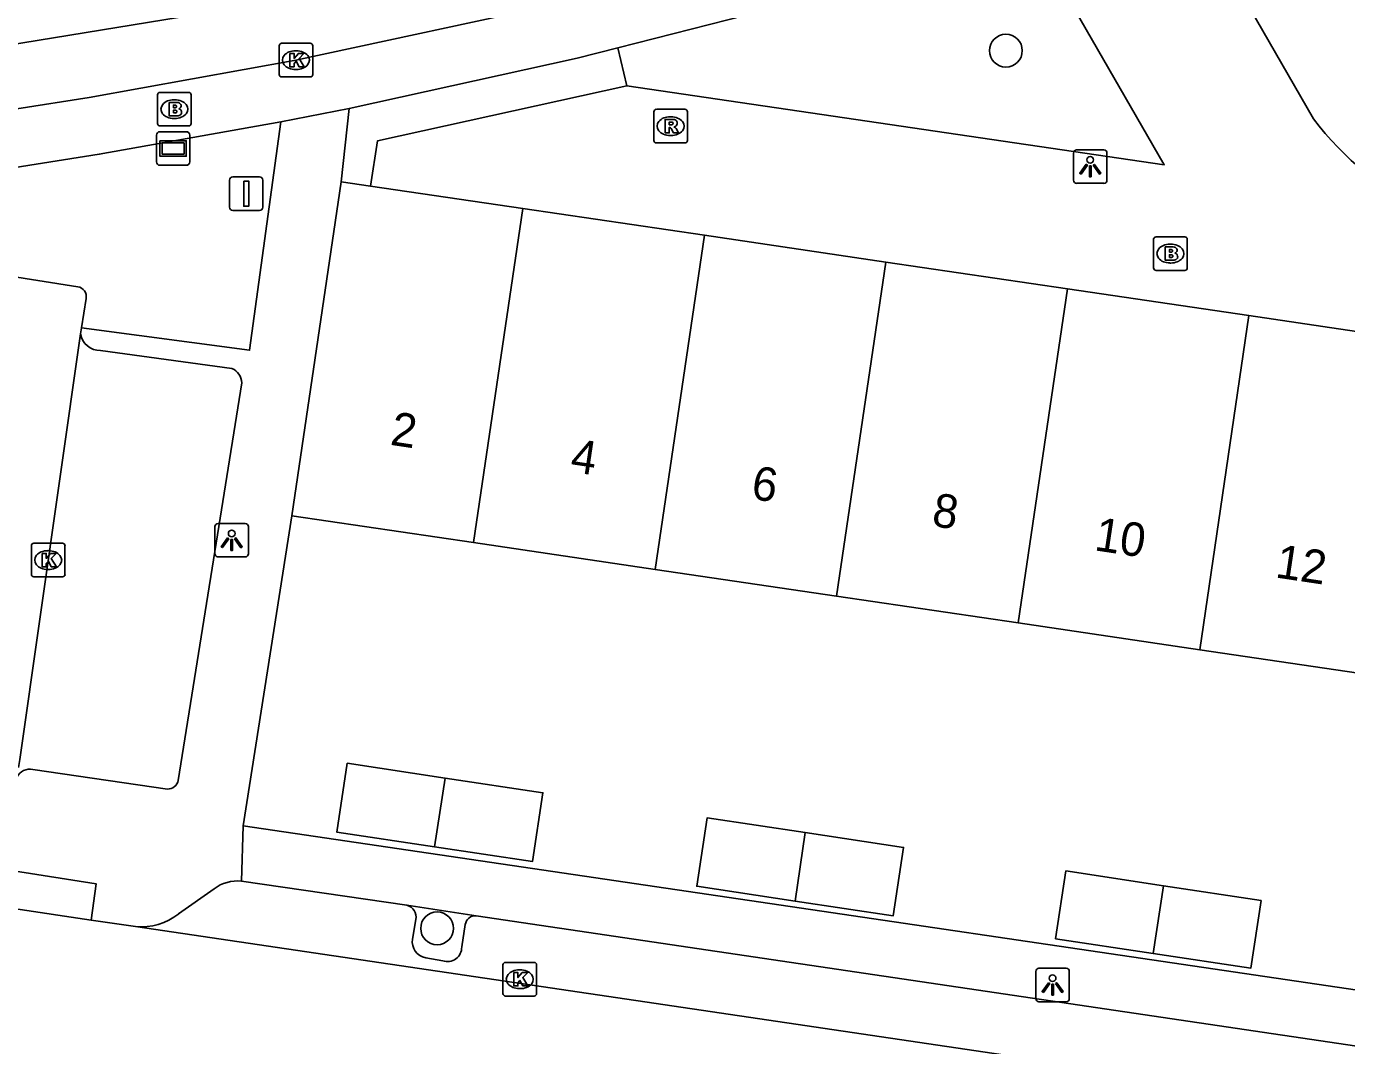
# Model space of a CAD drawing. Extents: x 164150 to 165261, y 382513 to 383432.
# Drawn here: x 164377.35 to 164416.63, y 383340.94 to 383371.28 of the extents above; entities that cross this region are included whole.
import ezdxf

# ---------------------------------------------------------------- set-up
doc = ezdxf.new("R2010")
doc.units = 0
for name, color, linetype in [('IMGEO_Boom', 7, 'Continuous'), ('IMGEO_Brandkraan', 7, 'Continuous'), ('IMGEO_Kolk', 7, 'Continuous'), ('IMGEO_Lichtpunt', 7, 'Continuous'), ('IMGEO_Pand', 7, 'Continuous'), ('IMGEO_Pand_nummerreeks', 7, 'Continuous'), ('IMGEO_Parkeervlak_open', 7, 'Continuous'), ('IMGEO_Rijbaan_lokaal_gesloten', 7, 'Continuous'), ('IMGEO_Rijbaan_lokaal_open', 7, 'Continuous'), ('IMGEO_Rioolput', 7, 'Continuous'), ('IMGEO_Verkeersbordpaal', 7, 'Continuous'), ('IMGEO_Verklikker', 7, 'Continuous'), ('IMGEO_Voetpad_op_trap', 7, 'Continuous'), ('IMGEO_Voetpad_open', 7, 'Continuous')]:
    doc.layers.add(name, color=color, linetype=linetype)

msp = doc.modelspace()

# ---------------------------------------------------------------- linework, layer by layer
at = {"layer": 'IMGEO_Boom'}
for centre in [(164406.495, 383370.556), (164389.572, 383344.434)]:
    msp.add_circle(centre, 0.489, dxfattribs=at)
at = {"layer": 'IMGEO_Brandkraan'}
for p, q in [((164381.254, 383368.389), (164381.254, 383369.241)), ((164381.329, 383369.315), (164382.181, 383369.315)), ((164382.255, 383369.241), (164382.255, 383368.389)), ((164381.742, 383369.095), (164381.767, 383369.095)), ((164381.765, 383368.535), (164381.74, 383368.535)), ((164382.181, 383368.315), (164381.329, 383368.315)), ((164410.89, 383364.09), (164410.89, 383364.942)), ((164410.965, 383365.016), (164411.817, 383365.016)), ((164411.891, 383364.942), (164411.891, 383364.09)), ((164411.378, 383364.796), (164411.403, 383364.796)), ((164411.401, 383364.236), (164411.376, 383364.236)), ((164411.817, 383364.016), (164410.965, 383364.016))]:
    msp.add_line(p, q, dxfattribs=at)
for points in [[(164381.254, 383368.389), (164381.254, 383369.241)], [(164381.329, 383369.315), (164382.181, 383369.315)], [(164382.255, 383369.241), (164382.255, 383368.389)], [(164381.602, 383369.015), (164381.602, 383368.615), (164381.815, 383368.615)], [(164381.833, 383369.015), (164381.602, 383369.015)], [(164381.781, 383368.934), (164381.727, 383368.934), (164381.727, 383368.858)], [(164381.727, 383368.858), (164381.78, 383368.858)], [(164381.789, 383368.782), (164381.727, 383368.782), (164381.727, 383368.701)], [(164381.727, 383368.701), (164381.789, 383368.701)], [(164382.181, 383368.315), (164381.329, 383368.315)], [(164410.89, 383364.09), (164410.89, 383364.942)], [(164410.965, 383365.016), (164411.817, 383365.016)], [(164411.891, 383364.942), (164411.891, 383364.09)], [(164411.238, 383364.716), (164411.238, 383364.316), (164411.451, 383364.316)], [(164411.469, 383364.716), (164411.238, 383364.716)], [(164411.417, 383364.635), (164411.363, 383364.635), (164411.363, 383364.559)], [(164411.363, 383364.559), (164411.416, 383364.559)], [(164411.425, 383364.483), (164411.363, 383364.483), (164411.363, 383364.402)], [(164411.363, 383364.402), (164411.425, 383364.402)], [(164411.817, 383364.016), (164410.965, 383364.016)]]:
    msp.add_lwpolyline(points, dxfattribs=at)
for centre, radius, start, end in [((164381.331, 383369.239), 0.0765, 91.552, 178.448), ((164381.331, 383369.239), 0.0765, 91.552, 178.448), ((164382.179, 383369.239), 0.0765, 1.552, 88.448), ((164382.179, 383369.239), 0.0765, 1.552, 88.448), ((164381.782, 383368.896), 0.0379, 267.8285, 90.9355), ((164381.837, 383368.87), 0.145, 59.4692, 91.5367), ((164381.862, 383368.917), 0.0922, 285.5137, 58.1501), ((164381.867, 383368.725), 0.105, 301.3115, 78.989), ((164381.79, 383368.741), 0.0404, 269.8759, 90.5077), ((164381.821, 383368.866), 0.251, 268.6676, 293.5347), ((164381.331, 383368.391), 0.0765, 181.552, 268.448), ((164381.331, 383368.391), 0.0765, 181.552, 268.448), ((164382.179, 383368.391), 0.0765, 271.552, 358.448), ((164382.179, 383368.391), 0.0765, 271.552, 358.448), ((164410.967, 383364.94), 0.0765, 91.552, 178.448), ((164410.967, 383364.94), 0.0765, 91.552, 178.448), ((164411.815, 383364.94), 0.0765, 1.552, 88.448), ((164411.815, 383364.94), 0.0765, 1.552, 88.448), ((164411.418, 383364.597), 0.0379, 267.8285, 90.9355), ((164411.473, 383364.571), 0.145, 59.4692, 91.5367), ((164411.498, 383364.618), 0.0922, 285.5137, 58.1501), ((164411.503, 383364.426), 0.105, 301.3115, 78.989), ((164411.426, 383364.442), 0.0404, 269.8759, 90.5077), ((164411.457, 383364.567), 0.251, 268.6676, 293.5347), ((164410.967, 383364.092), 0.0765, 181.552, 268.448), ((164410.967, 383364.092), 0.0765, 181.552, 268.448), ((164411.815, 383364.092), 0.0765, 271.552, 358.448), ((164411.815, 383364.092), 0.0765, 271.552, 358.448)]:
    msp.add_arc(centre, radius, start, end, dxfattribs=at)
for centre, major_axis, ratio, start_param, end_param in [((164381.741, 383368.815), (-0.387, 0.002), 0.722429, 4.712389, 7.853982), ((164381.766, 383368.815), (-0.39, 0.002), 0.717154, 1.570796, 4.712389), ((164411.377, 383364.516), (-0.387, 0.002), 0.722429, 4.712389, 7.853982), ((164411.402, 383364.516), (-0.39, 0.002), 0.717154, 1.570796, 4.712389)]:
    msp.add_ellipse(centre, major_axis=major_axis, ratio=ratio, start_param=start_param, end_param=end_param, dxfattribs=at)
at = {"layer": 'IMGEO_Kolk'}
for p, q in [((164384.871, 383369.849), (164384.871, 383370.701)), ((164384.946, 383370.775), (164385.798, 383370.775)), ((164385.359, 383370.555), (164385.384, 383370.555)), ((164385.872, 383370.701), (164385.872, 383369.849)), ((164385.798, 383369.775), (164384.946, 383369.775)), ((164385.382, 383369.995), (164385.357, 383369.995)), ((164377.574, 383355.895), (164378.426, 383355.895)), ((164377.499, 383354.969), (164377.499, 383355.821)), ((164377.987, 383355.675), (164378.012, 383355.675)), ((164378.5, 383355.821), (164378.5, 383354.969)), ((164378.01, 383355.115), (164377.985, 383355.115)), ((164378.426, 383354.895), (164377.574, 383354.895)), ((164391.53, 383342.493), (164391.53, 383343.345)), ((164391.605, 383343.419), (164392.457, 383343.419)), ((164392.531, 383343.345), (164392.531, 383342.493)), ((164392.018, 383343.199), (164392.043, 383343.199)), ((164392.041, 383342.639), (164392.016, 383342.639)), ((164392.457, 383342.419), (164391.605, 383342.419))]:
    msp.add_line(p, q, dxfattribs=at)
for points in [[(164384.871, 383369.849), (164384.871, 383370.701)], [(164384.946, 383370.775), (164385.798, 383370.775)], [(164385.192, 383370.475), (164385.315, 383370.475), (164385.315, 383370.324), (164385.445, 383370.475), (164385.609, 383370.475), (164385.463, 383370.324), (164385.616, 383370.075), (164385.464, 383370.075), (164385.379, 383370.239), (164385.315, 383370.172), (164385.315, 383370.075), (164385.192, 383370.075), (164385.192, 383370.475)], [(164385.872, 383370.701), (164385.872, 383369.849)], [(164385.798, 383369.775), (164384.946, 383369.775)], [(164377.574, 383355.895), (164378.426, 383355.895)], [(164377.499, 383354.969), (164377.499, 383355.821)], [(164377.82, 383355.595), (164377.943, 383355.595), (164377.943, 383355.444), (164378.073, 383355.595), (164378.237, 383355.595), (164378.091, 383355.444), (164378.244, 383355.195), (164378.092, 383355.195), (164378.007, 383355.359), (164377.943, 383355.292), (164377.943, 383355.195), (164377.82, 383355.195), (164377.82, 383355.595)], [(164378.5, 383355.821), (164378.5, 383354.969)], [(164378.426, 383354.895), (164377.574, 383354.895)], [(164391.53, 383342.493), (164391.53, 383343.345)], [(164391.605, 383343.419), (164392.457, 383343.419)], [(164392.531, 383343.345), (164392.531, 383342.493)], [(164391.851, 383343.119), (164391.974, 383343.119), (164391.974, 383342.968), (164392.104, 383343.119), (164392.268, 383343.119), (164392.122, 383342.968), (164392.275, 383342.719), (164392.123, 383342.719), (164392.038, 383342.883), (164391.974, 383342.816), (164391.974, 383342.719), (164391.851, 383342.719), (164391.851, 383343.119)], [(164392.457, 383342.419), (164391.605, 383342.419)]]:
    msp.add_lwpolyline(points, dxfattribs=at)
for centre, start, end in [((164384.948, 383370.699), 91.552, 178.448), ((164384.948, 383370.699), 91.552, 178.448), ((164385.796, 383370.699), 1.552, 88.448), ((164385.796, 383370.699), 1.552, 88.448), ((164384.948, 383369.851), 181.552, 268.448), ((164384.948, 383369.851), 181.552, 268.448), ((164385.796, 383369.851), 271.552, 358.448), ((164385.796, 383369.851), 271.552, 358.448), ((164377.576, 383355.819), 91.552, 178.448), ((164377.576, 383355.819), 91.552, 178.448), ((164378.424, 383355.819), 1.552, 88.448), ((164378.424, 383355.819), 1.552, 88.448), ((164377.576, 383354.971), 181.552, 268.448), ((164377.576, 383354.971), 181.552, 268.448), ((164378.424, 383354.971), 271.552, 358.448), ((164378.424, 383354.971), 271.552, 358.448), ((164391.607, 383343.343), 91.552, 178.448), ((164391.607, 383343.343), 91.552, 178.448), ((164392.455, 383343.343), 1.552, 88.448), ((164392.455, 383343.343), 1.552, 88.448), ((164391.607, 383342.495), 181.552, 268.448), ((164391.607, 383342.495), 181.552, 268.448), ((164392.455, 383342.495), 271.552, 358.448), ((164392.455, 383342.495), 271.552, 358.448)]:
    msp.add_arc(centre, 0.0765, start, end, dxfattribs=at)
for centre, major_axis, ratio, start_param, end_param in [((164385.358, 383370.275), (-0.387, 0.002), 0.722429, 4.712389, 7.853982), ((164385.383, 383370.275), (-0.39, 0.002), 0.717154, 1.570796, 4.712389), ((164377.986, 383355.395), (-0.387, 0.002), 0.722429, 4.712389, 7.853982), ((164378.011, 383355.395), (-0.39, 0.002), 0.717154, 1.570796, 4.712389), ((164392.017, 383342.919), (-0.387, 0.002), 0.722429, 4.712389, 7.853982), ((164392.042, 383342.919), (-0.39, 0.002), 0.717154, 1.570796, 4.712389)]:
    msp.add_ellipse(centre, major_axis=major_axis, ratio=ratio, start_param=start_param, end_param=end_param, dxfattribs=at)
at = {"layer": 'IMGEO_Lichtpunt'}
for p, q in [((164408.507, 383367.509), (164408.507, 383366.702)), ((164408.507, 383367.509), (164408.507, 383366.702)), ((164409.409, 383367.604), (164408.601, 383367.604)), ((164409.409, 383367.604), (164408.601, 383367.604)), ((164409.503, 383366.702), (164409.503, 383367.509)), ((164409.503, 383366.702), (164409.503, 383367.509)), ((164408.601, 383366.608), (164409.409, 383366.608)), ((164408.601, 383366.608), (164409.409, 383366.608)), ((164382.961, 383356.39), (164382.961, 383355.583)), ((164382.961, 383356.39), (164382.961, 383355.583)), ((164383.863, 383356.485), (164383.055, 383356.485)), ((164383.863, 383356.485), (164383.055, 383356.485)), ((164383.957, 383355.583), (164383.957, 383356.39)), ((164383.957, 383355.583), (164383.957, 383356.39)), ((164383.055, 383355.489), (164383.863, 383355.489)), ((164383.055, 383355.489), (164383.863, 383355.489)), ((164407.387, 383343.152), (164407.387, 383342.345)), ((164407.387, 383343.152), (164407.387, 383342.345)), ((164408.289, 383343.247), (164407.481, 383343.247)), ((164408.289, 383343.247), (164407.481, 383343.247)), ((164408.383, 383342.345), (164408.383, 383343.152)), ((164408.383, 383342.345), (164408.383, 383343.152)), ((164407.481, 383342.251), (164408.289, 383342.251)), ((164407.481, 383342.251), (164408.289, 383342.251))]:
    msp.add_line(p, q, dxfattribs=at)
for points in [[(164408.881, 383367.173), (164408.92, 383367.145), (164408.732, 383366.883), (164408.694, 383366.91), (164408.881, 383367.173)], [(164408.983, 383367.125), (164409.03, 383367.125), (164409.03, 383366.803), (164408.983, 383366.803), (164408.983, 383367.125)], [(164409.093, 383367.145), (164409.131, 383367.172), (164409.318, 383366.91), (164409.279, 383366.882), (164409.093, 383367.145)], [(164383.335, 383356.054), (164383.374, 383356.026), (164383.186, 383355.764), (164383.148, 383355.791), (164383.335, 383356.054)], [(164383.437, 383356.006), (164383.484, 383356.006), (164383.484, 383355.684), (164383.437, 383355.684), (164383.437, 383356.006)], [(164383.547, 383356.026), (164383.585, 383356.053), (164383.772, 383355.791), (164383.733, 383355.763), (164383.547, 383356.026)], [(164407.761, 383342.816), (164407.8, 383342.788), (164407.612, 383342.526), (164407.574, 383342.553), (164407.761, 383342.816)], [(164407.863, 383342.768), (164407.91, 383342.768), (164407.91, 383342.446), (164407.863, 383342.446), (164407.863, 383342.768)], [(164407.973, 383342.788), (164408.011, 383342.815), (164408.198, 383342.553), (164408.159, 383342.525), (164407.973, 383342.788)]]:
    msp.add_lwpolyline(points, dxfattribs=at)
for centre in [(164409.006, 383367.307), (164383.46, 383356.188), (164407.886, 383342.95)]:
    msp.add_circle(centre, 0.0994, dxfattribs=at)
for centre, start, end in [((164408.601, 383367.509), 90, 180), ((164408.601, 383367.509), 90, 180), ((164409.409, 383367.509), 0, 90), ((164409.409, 383367.509), 0, 90), ((164408.601, 383366.702), 180, 270), ((164408.601, 383366.702), 180, 270), ((164409.409, 383366.702), 270, 0), ((164409.409, 383366.702), 270, 360), ((164383.055, 383356.39), 90, 180), ((164383.055, 383356.39), 90, 180), ((164383.863, 383356.39), 0, 90), ((164383.863, 383356.39), 0, 90), ((164383.055, 383355.583), 180, 270), ((164383.055, 383355.583), 180, 270), ((164383.863, 383355.583), 270, 0), ((164383.863, 383355.583), 270, 360), ((164407.481, 383343.152), 90, 180), ((164407.481, 383343.152), 90, 180), ((164408.289, 383343.152), 0, 90), ((164408.289, 383343.152), 0, 90), ((164407.481, 383342.345), 180, 270), ((164407.481, 383342.345), 180, 270), ((164408.289, 383342.345), 270, 0), ((164408.289, 383342.345), 270, 360)]:
    msp.add_arc(centre, 0.0946, start, end, dxfattribs=at)
at = {"layer": 'IMGEO_Pand'}
for points in [[(164385.254, 383356.711), (164386.721, 383366.655)], [(164386.721, 383366.655), (164387.595, 383366.526)], [(164387.595, 383366.526), (164392.122, 383365.858)], [(164392.122, 383365.858), (164390.656, 383355.914)], [(164392.122, 383365.858), (164397.524, 383365.061)], [(164397.524, 383365.061), (164396.057, 383355.118)], [(164397.524, 383365.061), (164402.925, 383364.265)], [(164401.459, 383354.321), (164402.925, 383364.265)], [(164402.925, 383364.265), (164408.327, 383363.468)], [(164406.86, 383353.525), (164408.327, 383363.468)], [(164408.327, 383363.468), (164413.728, 383362.671)], [(164413.728, 383362.671), (164412.262, 383352.728)], [(164413.728, 383362.671), (164419.13, 383361.874)], [(164385.254, 383356.711), (164390.656, 383355.914)], [(164390.656, 383355.914), (164396.057, 383355.118)], [(164396.057, 383355.118), (164401.459, 383354.321)], [(164401.459, 383354.321), (164406.86, 383353.525)], [(164406.86, 383353.525), (164412.262, 383352.728)], [(164412.262, 383352.728), (164417.663, 383351.931)], [(164389.807, 383348.908), (164386.896, 383349.346), (164386.587, 383347.297), (164389.499, 383346.859)], [(164389.499, 383346.859), (164392.41, 383346.42), (164392.719, 383348.469), (164389.807, 383348.908)], [(164389.807, 383348.908), (164389.499, 383346.859)], [(164400.528, 383347.282), (164397.605, 383347.721), (164397.299, 383345.686), (164400.223, 383345.247)], [(164400.223, 383345.247), (164403.146, 383344.807), (164403.452, 383346.842), (164400.528, 383347.282)], [(164400.528, 383347.282), (164400.223, 383345.247)], [(164411.186, 383345.7), (164408.283, 383346.141), (164407.977, 383344.125), (164410.88, 383343.685)], [(164411.186, 383345.7), (164410.88, 383343.685)], [(164410.88, 383343.685), (164413.783, 383343.244), (164414.089, 383345.26), (164411.186, 383345.7)]]:
    msp.add_lwpolyline(points, dxfattribs=at)
at = {"layer": 'IMGEO_Parkeervlak_open'}
for points in [[(164388.943, 383344.699), (164388.839, 383344.111)], [(164390.304, 383343.881), (164390.411, 383344.545)], [(164389.233, 383343.56), (164389.74, 383343.469)]]:
    msp.add_lwpolyline(points, dxfattribs=at)
for centre, radius, start, end in [((164388.581, 383344.764), 0.367, 349.8539, 75.8775), ((164390.709, 383344.508), 0.301, 85.8759, 172.9559), ((164389.312, 383344.033), 0.479, 170.6112, 260.5231), ((164389.878, 383343.872), 0.426, 251.1423, 1.1537)]:
    msp.add_arc(centre, radius, start, end, dxfattribs=at)
at = {"layer": 'IMGEO_Rijbaan_lokaal_gesloten'}
for points in [[(164434.664, 383386.795), (164431.134, 383385.12), (164423.565, 383381.867), (164417.783, 383379.568), (164412.246, 383377.557), (164405.377, 383375.292), (164399.239, 383373.497), (164393.394, 383372), (164385.372, 383370.275), (164379.217, 383369.164), (164364.147, 383366.805), (164355.96, 383365.609), (164347.021, 383364.613), (164333.574, 383363.59), (164329.584, 383363.288), (164324.642, 383362.347), (164322.532, 383361.699), (164314.821, 383358.779), (164313.606, 383358.425)], [(164313.12, 383360.215), (164324.281, 383363.805), (164329.441, 383365.032), (164345.601, 383366.353), (164363.616, 383368.567), (164384.72, 383372.013), (164391.019, 383373.335), (164397.192, 383374.879), (164403.181, 383376.603), (164414.799, 383380.452), (164419.832, 383382.287)]]:
    msp.add_lwpolyline(points, dxfattribs=at)
at = {"layer": 'IMGEO_Rijbaan_lokaal_open'}
for points in [[(164378.878, 383363.528), (164373.299, 383364.408)], [(164378.99, 383362.31), (164379.126, 383363.181)], [(164378.99, 383362.31), (164378.962, 383362.129)], [(164378.962, 383362.129), (164377.152, 383349.457), (164377.115, 383349.22)], [(164379.283, 383344.677), (164376.965, 383345.026)], [(164379.283, 383344.677), (164380.597, 383344.493)], [(164424.122, 383338.051), (164380.597, 383344.493)]]:
    msp.add_lwpolyline(points, dxfattribs=at)
msp.add_arc((164378.837, 383363.236), 0.295, 349.1936, 81.913, dxfattribs=at)
at = {"layer": 'IMGEO_Rioolput'}
for p, q in [((164396.02, 383367.884), (164396.02, 383368.736)), ((164396.095, 383368.81), (164396.947, 383368.81)), ((164396.508, 383368.59), (164396.533, 383368.59)), ((164397.021, 383368.736), (164397.021, 383367.884)), ((164396.947, 383367.81), (164396.095, 383367.81)), ((164396.531, 383368.03), (164396.506, 383368.03))]:
    msp.add_line(p, q, dxfattribs=at)
for points in [[(164396.02, 383367.884), (164396.02, 383368.736)], [(164396.095, 383368.81), (164396.947, 383368.81)], [(164396.609, 383368.508), (164396.357, 383368.51), (164396.357, 383368.11)], [(164397.021, 383368.736), (164397.021, 383367.884)], [(164396.357, 383368.11), (164396.481, 383368.11), (164396.481, 383368.272), (164396.492, 383368.272)], [(164396.535, 383368.429), (164396.481, 383368.429), (164396.481, 383368.348)], [(164396.481, 383368.348), (164396.533, 383368.348)], [(164396.539, 383368.243), (164396.61, 383368.11), (164396.75, 383368.11), (164396.685, 383368.236)], [(164396.947, 383367.81), (164396.095, 383367.81)]]:
    msp.add_lwpolyline(points, dxfattribs=at)
for centre, radius, start, end in [((164396.097, 383368.734), 0.0765, 91.552, 178.448), ((164396.097, 383368.734), 0.0765, 91.552, 178.448), ((164396.608, 383368.398), 0.109, 350.3612, 89.416), ((164396.945, 383368.734), 0.0765, 1.552, 88.448), ((164396.945, 383368.734), 0.0765, 1.552, 88.448), ((164396.491, 383368.219), 0.0533, 26.0293, 88.6989), ((164396.517, 383368.537), 0.19, 274.7715, 282.9687), ((164396.541, 383368.333), 0.0964, 77.0061, 93.1865), ((164396.555, 383368.39), 0.0378, 276.6634, 79.6772), ((164396.606, 383368.398), 0.112, 277.5842, 350.9817), ((164396.59, 383368.183), 0.108, 29.5134, 73.7905), ((164396.097, 383367.886), 0.0765, 181.552, 268.448), ((164396.097, 383367.886), 0.0765, 181.552, 268.448), ((164396.945, 383367.886), 0.0765, 271.552, 358.448), ((164396.945, 383367.886), 0.0765, 271.552, 358.448)]:
    msp.add_arc(centre, radius, start, end, dxfattribs=at)
for centre, major_axis, ratio, start_param, end_param in [((164396.507, 383368.31), (-0.387, 0.002), 0.722429, 4.712389, 7.853982), ((164396.532, 383368.31), (-0.39, 0.002), 0.717154, 1.570796, 4.712389)]:
    msp.add_ellipse(centre, major_axis=major_axis, ratio=ratio, start_param=start_param, end_param=end_param, dxfattribs=at)
at = {"layer": 'IMGEO_Verkeersbordpaal'}
for p, q in [((164383.398, 383365.898), (164383.398, 383366.698)), ((164383.398, 383366.698), (164383.398, 383365.898)), ((164383.498, 383366.798), (164384.288, 383366.798)), ((164384.288, 383366.798), (164383.498, 383366.798)), ((164384.388, 383366.698), (164384.388, 383365.898)), ((164384.388, 383365.898), (164384.388, 383366.698)), ((164384.288, 383365.798), (164383.498, 383365.798)), ((164383.498, 383365.798), (164384.288, 383365.798))]:
    msp.add_line(p, q, dxfattribs=at)
msp.add_lwpolyline([(164383.818, 383366.673), (164383.968, 383366.673), (164383.968, 383365.923), (164383.818, 383365.923), (164383.818, 383366.673)], dxfattribs=at)
for centre, start, end in [((164383.498, 383366.698), 90, 180), ((164383.498, 383366.698), 90, 180), ((164384.288, 383366.698), 0, 90), ((164384.288, 383366.698), 360, 90), ((164383.498, 383365.898), 180, 270), ((164383.498, 383365.898), 180, 270), ((164384.288, 383365.898), 270, 0), ((164384.288, 383365.898), 270, 0)]:
    msp.add_arc(centre, 0.1, start, end, dxfattribs=at)
at = {"layer": 'IMGEO_Verklikker'}
for p, q in [((164381.221, 383367.244), (164381.221, 383368.044)), ((164381.221, 383368.044), (164381.221, 383367.244)), ((164381.321, 383368.144), (164382.111, 383368.144)), ((164382.111, 383368.144), (164381.321, 383368.144)), ((164382.211, 383368.044), (164382.211, 383367.244)), ((164382.211, 383367.244), (164382.211, 383368.044)), ((164382.111, 383367.144), (164381.321, 383367.144)), ((164381.321, 383367.144), (164382.111, 383367.144))]:
    msp.add_line(p, q, dxfattribs=at)
for points in [[(164381.322, 383367.876), (164382.11, 383367.876), (164382.11, 383367.412), (164381.322, 383367.412), (164381.322, 383367.876)], [(164381.387, 383367.811), (164381.387, 383367.477), (164382.045, 383367.477), (164382.045, 383367.811), (164381.387, 383367.811)]]:
    msp.add_lwpolyline(points, dxfattribs=at)
for centre, start, end in [((164381.321, 383368.044), 90, 180), ((164381.321, 383368.044), 90, 180), ((164382.111, 383368.044), 0, 90), ((164382.111, 383368.044), 360, 90), ((164381.321, 383367.244), 180, 270), ((164381.321, 383367.244), 180, 270), ((164382.111, 383367.244), 270, 0), ((164382.111, 383367.244), 270, 0)]:
    msp.add_arc(centre, 0.1, start, end, dxfattribs=at)
at = {"layer": 'IMGEO_Voetpad_op_trap'}
msp.add_lwpolyline([(164395.215, 383369.511), (164394.953, 383370.643)], dxfattribs=at)
at = {"layer": 'IMGEO_Voetpad_open'}
for points in [[(164415.65, 383368.528), (164411.836, 383375.154), (164411.731, 383375.499)], [(164394.953, 383370.643), (164399.861, 383371.892), (164405.938, 383373.629), (164407.24, 383374.055)], [(164407.24, 383374.055), (164411.208, 383367.163), (164395.215, 383369.511)], [(164386.952, 383368.836), (164393.735, 383370.333), (164394.953, 383370.643)], [(164395.215, 383369.511), (164387.797, 383367.868), (164387.595, 383366.526)], [(164384.924, 383368.441), (164386.952, 383368.836)], [(164386.721, 383366.655), (164386.952, 383368.836)], [(164357.183, 383364.054), (164357.32, 383364.068), (164364.576, 383365.104), (164379.521, 383367.475), (164384.924, 383368.441)], [(164384.924, 383368.441), (164383.994, 383361.641), (164378.99, 383362.31)], [(164379.557, 383361.629), (164383.469, 383361.096)], [(164383.762, 383360.673), (164381.87, 383348.839)], [(164383.799, 383347.483), (164385.254, 383356.711)], [(164428.467, 383350.338), (164427.117, 383341.092), (164383.799, 383347.483)], [(164381.547, 383348.576), (164377.541, 383349.161)], [(164383.752, 383345.842), (164383.799, 383347.483)], [(164376.967, 383346.15), (164379.423, 383345.762), (164379.283, 383344.677)], [(164383.752, 383345.842), (164388.671, 383345.12)], [(164381.882, 383344.862), (164382.934, 383345.612)], [(164388.671, 383345.12), (164390.731, 383344.808)], [(164390.731, 383344.808), (164424.372, 383339.822)]]:
    msp.add_lwpolyline(points, dxfattribs=at)
for centre, radius, start, end in [((164423.021, 383374.073), 9.224, 216.9511, 244.6217), ((164379.551, 383362.226), 0.597, 189.3644, 270.5525), ((164383.262, 383360.64), 0.501, 3.7918, 65.6267), ((164377.454, 383348.737), 0.433, 78.3583, 152.5117), ((164381.544, 383348.909), 0.333, 270.4363, 347.8716), ((164383.65, 383344.635), 1.212, 85.1799, 126.2293), ((164380.781, 383346.274), 1.791, 264.1003, 307.9435)]:
    msp.add_arc(centre, radius, start, end, dxfattribs=at)

# ---------------------------------------------------------------- texts
at = {"layer": 'IMGEO_Pand_nummerreeks'}
for s, rotation, p in [('2', 351.4766, (164388.151, 383358.829)), ('4', 351.4744, (164393.507, 383358.026)), ('6', 351.4744, (164398.888, 383357.22)), ('8', 351.4744, (164404.264, 383356.414)), ('10', 351.4744, (164409.1, 383355.689)), ('12', 351.4744, (164414.484, 383354.882))]:
    msp.add_text(s, height=1, rotation=rotation, dxfattribs=at).set_placement(p)

doc.saveas('drawing.dxf')
